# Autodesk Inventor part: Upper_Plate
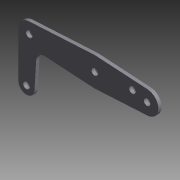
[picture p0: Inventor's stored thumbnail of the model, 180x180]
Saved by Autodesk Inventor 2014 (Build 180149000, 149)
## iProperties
Shininess: 15.0
Length Units: 11272
Angle Units: 11279
Time Units: 11290
Mass Units: 11283
Length Display Precision: 2
Angle Display Precision: 1
Compacted: True
Created: 1999-05
Part Number: Upper_Plate
Document SubType Name: Modeling
Designer: Administrator
Density: 7.86 g/cm^3
Material: Steel, Mild
Appearance: Metal - Steel 2
Density: 7.86
Volumn: 11.910644871161018
Area: 90.04134983224549
PropertySet Name: Model Information
Control State: 0
Master: False
Checked Out: False
Author: Administrator
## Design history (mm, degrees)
node "y-z Plane"
  node "x-z Plane"
  node "x-y Plane"
node "Extrusion1" dims "d10" = 3.175, "d11" = 0
  sketch "Sketch1"
    geometry: L1 (-74.168, -44.756)-(-74.168, -0.306); L2 (-64.097, 10.346)-(-0.797, 13.896); L3 (0.882, 13.891)-(51.487, 10.747); L4 (51.42, -11.362)-(0.797, -14.202); L5 (-0.882, -14.197)-(-48.27, -11.253); L6 (-56.791, -18.777)-(-58.435, -45.244); L7 (0, 27.279)-(0, -66.228) reference; L8 (-103.926, 0)-(89.546, 0) reference; A1 r 10.668 centre (-63.5, -0.306) between (-64.097, 10.346) and (-74.168, -0.306); A2 r 11.074 centre (50.8, -0.306) between (51.42, -11.362) and (51.487, 10.747); A3 r 8.038 centre (-48.768, -19.275) between (-48.27, -11.253) and (-56.791, -18.777); A4 r 7.874 centre (-66.294, -44.756) between (-74.168, -44.756) and (-58.435, -45.244); A5 r 14.224 centre (0, -0.306) between (0.882, 13.891) and (-0.797, 13.896); A6 r 14.224 centre (0, 0) between (-0.882, -14.197) and (0.797, -14.202); 1 further point
    constraints: 12 end point, 12 point on circle, 12 tangent, 6 centre point, 2 horizontal alignment, 2 parallel, 1 coincident, 1 equal radius, 1 perpendicular, 1 vertical, 1 vertical alignment
    dimensions: "d0" = 14.224 radius of A5; "d1" = 10.668 radius of A1; "d2" = 18.96975 vertical distance of A3.centre A1.centre; "d3" = 7.874 radius of A4; "d4" = 44.45 vertical distance of A1.centre A4.centre; "d5" = 17.526 horizontal distance of A3.centre A4.centre; "d8" = 63.5 distance of A1.centre A5.centre; "d9" = 114.3 distance of A2.centre A1.centre
node "Hole1" dims "d14" = 6.35, "d15" = 9.525, "d16" = 6.35, "d17" = 60 deg, "d18" = 19.05, "d19" = 118 deg
  sketch "Sketch2"
    geometry: A1 r 7.874 centre (-66.294, -44.756) between (-74.168, -44.756) and (-58.435, -45.244) reference; A2 r 11.074 centre (50.8, -0.306) between (51.42, -11.362) and (51.487, 10.747) reference; A3 r 14.224 centre (0, -0.306) between (0.882, 13.891) and (-0.797, 13.896) reference; A4 r 10.668 centre (-63.5, -0.306) between (-64.097, 10.346) and (-74.168, -0.306) reference; 1 further point
    dimensions: "d12" = 36.576 horizontal distance of A3.centre point (36.576, 2.742); "d13" = 3.048 vertical distance of A3.centre point (36.576, 2.742)
body "Solid1"
